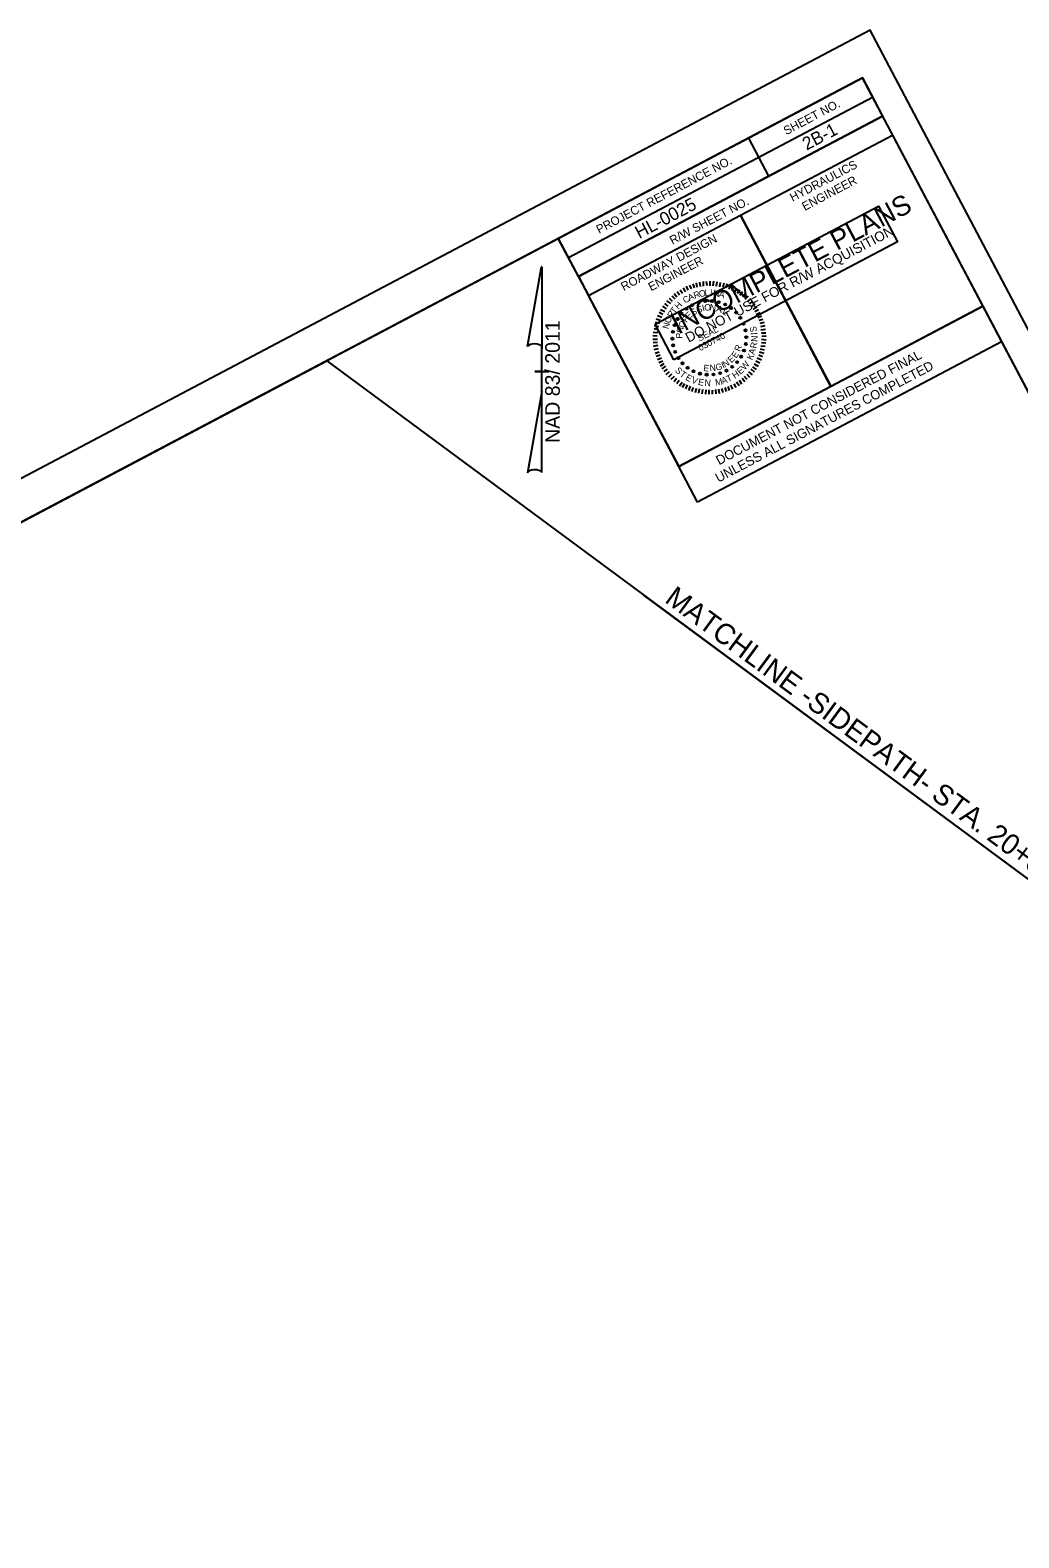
# Model space of a CAD drawing. Extents: x 1487051 to 1489051, y 497582 to 499336.
# Drawn here: x 1488051 to 1488626, y 498459 to 499336 of the extents above; entities that cross this region are included whole.
import ezdxf

# ---------------------------------------------------------------- set-up
doc = ezdxf.new("R2010")
doc.units = 0
for name, color, linetype in [('Matchline', 7, 'Continuous'), ('Matchline Text', 7, 'Continuous'), ('Old_Level_9', 7, 'Continuous'), ('Prop North Arrow NAD83 for Plan Sheets CELL', 7, 'Continuous'), ('Sheet Border Standard 30in CELL', 7, 'Continuous'), ('Sheet Clip Boundary CELL', 7, 'Continuous'), ('Sheet Data Field CELL', 7, 'Continuous'), ('Sheet Plan CELL', 7, 'Continuous'), ('Sheet Plot Border Outside CELL', 7, 'Continuous'), ('Sheet Sticker Exception Certification CELL', 7, 'Continuous'), ('Sheet Sticker Incomplete CELL', 7, 'Continuous')]:
    doc.layers.add(name, color=color, linetype=linetype)

msp = doc.modelspace()

# ---------------------------------------------------------------- linework, layer by layer
at = {"layer": 'Matchline'}
msp.add_line((1488759.65, 498747.81), (1488408.23, 499007.51), dxfattribs=at)
at = {"layer": 'Old_Level_9'}
for p, q in [((1488424.21, 499181.82), (1488425.99, 499179.94)), ((1488425.7, 499183.06), (1488427.26, 499181.18)), ((1488427.42, 499184.31), (1488428.72, 499182.28)), ((1488429.05, 499185.29), (1488430.44, 499183.3)), ((1488430.82, 499186.44), (1488432.03, 499184.14)), ((1488432.67, 499187.42), (1488433.62, 499184.98)), ((1488434.49, 499188.05), (1488435.44, 499185.83)), ((1488436.49, 499188.76), (1488437.17, 499186.41)), ((1488438.36, 499189.29), (1488438.86, 499186.85)), ((1488440.32, 499189.65), (1488440.82, 499187.2)), ((1488442.45, 499190.1), (1488442.51, 499187.42)), ((1488444.33, 499190.19), (1488444.61, 499187.73)), ((1488446.3, 499190.32), (1488446.36, 499187.64)), ((1488448.44, 499190.32), (1488448.14, 499187.68)), ((1488450.47, 499189.92), (1488450.07, 499187.45)), ((1488452.44, 499189.61), (1488451.96, 499187.09)), ((1488454.46, 499189.2), (1488453.89, 499186.87)), ((1488456.31, 499188.71), (1488455.6, 499186.19)), ((1488458.29, 499187.95), (1488457.36, 499185.64)), ((1488460.19, 499187.14), (1488458.99, 499184.92)), ((1488461.91, 499186.24), (1488460.71, 499184.02)), ((1488463.68, 499185.25), (1488462.34, 499183.07)), ((1488465.4, 499184.12), (1488463.79, 499182.03)), ((1488466.9, 499182.99), (1488465.52, 499180.91)), ((1488417.76, 499173.9), (1488420.12, 499172.65)), ((1488418.88, 499175.85), (1488421.07, 499174.28)), ((1488420.1, 499177.39), (1488421.97, 499175.78)), ((1488421.23, 499178.89), (1488423.41, 499177.33)), ((1488422.81, 499180.41), (1488424.55, 499178.61)), ((1488468.59, 499181.51), (1488466.66, 499179.59)), ((1488470.01, 499180.11), (1488468.12, 499178.32)), ((1488471.34, 499178.66), (1488469.36, 499177.05)), ((1488472.49, 499177.12), (1488470.6, 499175.56)), ((1488473.65, 499175.36), (1488471.49, 499173.88)), ((1488474.72, 499173.55), (1488472.51, 499172.38)), ((1488414.08, 499164.6), (1488416.55, 499163.98)), ((1488414.66, 499166.49), (1488417.05, 499165.83)), ((1488415.2, 499168.47), (1488417.5, 499167.54)), ((1488416.01, 499170.37), (1488418.4, 499169.26)), ((1488416.86, 499172.18), (1488419.12, 499171.11)), ((1488475.6, 499171.87), (1488473.39, 499170.7)), ((1488476.5, 499169.97), (1488474.28, 499169.02)), ((1488477.3, 499168.02), (1488474.94, 499167.34)), ((1488477.92, 499166.19), (1488475.38, 499165.65)), ((1488478.37, 499164.28), (1488475.83, 499163.73)), ((1488413.27, 499158.63), (1488415.82, 499158.51)), ((1488413.27, 499156.49), (1488415.96, 499156.55)), ((1488413.5, 499160.56), (1488416.05, 499160.44)), ((1488413.85, 499162.67), (1488416.28, 499162.14)), ((1488478.77, 499162.23), (1488476.05, 499161.81)), ((1488479, 499160.09), (1488476.49, 499160.12)), ((1488479.08, 499156.07), (1488476.49, 499156.28)), ((1488479.08, 499158.21), (1488476.62, 499158.16)), ((1488413.41, 499154.52), (1488416, 499154.76)), ((1488413.59, 499152.47), (1488416.26, 499152.97)), ((1488413.94, 499150.51), (1488416.48, 499151.06)), ((1488414.48, 499148.42), (1488416.93, 499149.14)), ((1488415.1, 499146.6), (1488417.45, 499147.5)), ((1488477.11, 499146.32), (1488474.85, 499147.16)), ((1488477.74, 499148.12), (1488475.26, 499148.96)), ((1488478.23, 499150.19), (1488475.8, 499150.72)), ((1488478.63, 499152.21), (1488476.12, 499152.47)), ((1488479.04, 499154.23), (1488476.35, 499154.4)), ((1488415.91, 499144.65), (1488418.25, 499145.77)), ((1488416.71, 499142.92), (1488419.01, 499143.91)), ((1488417.69, 499141.06), (1488419.8, 499142.41)), ((1488418.71, 499139.34), (1488420.87, 499140.82)), ((1488419.82, 499137.66), (1488421.84, 499139.19)), ((1488472.43, 499137.4), (1488470.34, 499139.01)), ((1488473.51, 499138.99), (1488471.47, 499140.51)), ((1488474.64, 499140.71), (1488472.28, 499141.96)), ((1488475.45, 499142.61), (1488473.19, 499143.68)), ((1488476.44, 499144.38), (1488473.95, 499145.44)), ((1488421.02, 499136.04), (1488422.95, 499137.73)), ((1488422.44, 499134.64), (1488424.28, 499136.29)), ((1488423.94, 499133.28), (1488425.74, 499135.02)), ((1488425.58, 499131.89), (1488427.06, 499133.8)), ((1488427.09, 499130.76), (1488428.52, 499132.76)), ((1488428.77, 499129.5), (1488430.24, 499131.63)), ((1488430.4, 499128.55), (1488431.74, 499130.73)), ((1488432.39, 499127.57), (1488433.41, 499129.91)), ((1488434.2, 499126.71), (1488435.04, 499129.19)), ((1488459.81, 499127.46), (1488458.69, 499129.8)), ((1488461.72, 499128.35), (1488460.55, 499130.56)), ((1488463.35, 499129.33), (1488461.96, 499131.53)), ((1488465.03, 499130.44), (1488463.64, 499132.42)), ((1488466.74, 499131.68), (1488465.13, 499133.66)), ((1488468.19, 499133.01), (1488466.54, 499134.85)), ((1488469.68, 499134.25), (1488468.03, 499136.09)), ((1488471.12, 499135.81), (1488469.07, 499137.55)), ((1488436, 499126.08), (1488436.89, 499128.47)), ((1488438.07, 499125.59), (1488438.6, 499128.02)), ((1488439.91, 499125.09), (1488440.35, 499127.7)), ((1488441.94, 499124.69), (1488442.28, 499127.25)), ((1488444.04, 499124.56), (1488444.16, 499127.11)), ((1488446.01, 499124.47), (1488446, 499127.06)), ((1488448.02, 499124.51), (1488447.97, 499126.97)), ((1488450.08, 499124.69), (1488449.84, 499127.28)), ((1488452.08, 499124.96), (1488451.67, 499127.46)), ((1488454.13, 499125.59), (1488453.45, 499127.94)), ((1488456.04, 499126.03), (1488455.32, 499128.48)), ((1488457.86, 499126.65), (1488457.01, 499128.92))]:
    msp.add_line(p, q, dxfattribs=at)
for centre in [(1488432.81, 499174.19), (1488436.14, 499176.35), (1488439.81, 499177.86), (1488443.69, 499178.66), (1488447.66, 499178.74), (1488451.57, 499178.09), (1488455.29, 499176.73), (1488458.71, 499174.71), (1488425.91, 499164.67), (1488427.61, 499168.25), (1488429.93, 499171.47), (1488461.69, 499172.1), (1488464.14, 499168.98), (1488465.98, 499165.47), (1488424.62, 499156.88), (1488424.9, 499160.83), (1488467.14, 499161.68), (1488467.58, 499157.74), (1488425.06, 499152.94), (1488426.22, 499149.15), (1488464.59, 499146.36), (1488466.29, 499149.95), (1488467.3, 499153.78), (1488428.06, 499145.63), (1488430.51, 499142.52), (1488433.5, 499139.91), (1488436.91, 499137.89), (1488456.06, 499138.27), (1488459.39, 499140.42), (1488462.27, 499143.15), (1488440.63, 499136.53), (1488444.54, 499135.88), (1488448.51, 499135.96), (1488452.39, 499136.76)]:
    msp.add_circle(centre, 0.63, dxfattribs=at)
at = {"layer": 'Prop North Arrow NAD83 for Plan Sheets CELL'}
for p, q in [((1488340.33, 499152.33), (1488348.53, 499198.68)), ((1488348.58, 499198.68), (1488348.53, 499198.68)), ((1488348.58, 499198.68), (1488348.53, 499198.68)), ((1488348.58, 499198.68), (1488348.58, 499150.88)), ((1488348.58, 499126.08), (1488348.58, 499152.28)), ((1488348.58, 499150.88), (1488348.58, 499152.23)), ((1488344.58, 499137.68), (1488344.53, 499137.68)), ((1488348.13, 499137.68), (1488344.58, 499137.68)), ((1488344.63, 499137.68), (1488352.63, 499137.68)), ((1488348.58, 499126.08), (1488340.23, 499078.83)), ((1488348.63, 499079.03), (1488348.58, 499126.08))]:
    msp.add_line(p, q, dxfattribs=at)
for centre, start_param, end_param in [((1488344.46, 499151.83), 0.216388, 2.908219), ((1488344.46, 499078.66), 0.201328, 3.141593)]:
    msp.add_ellipse(centre, major_axis=(4.23, -0.03), ratio=0.461098, start_param=start_param, end_param=end_param, dxfattribs=at)
at = {"layer": 'Sheet Border Standard 30in CELL'}
msp.add_line((1488369.9, 499192.95), (1488375.74, 499181.9), dxfattribs=at)
at = {"layer": 'Sheet Clip Boundary CELL'}
msp.add_lwpolyline([(1487208.66, 498608.09), (1488223.53, 499144), (1488876.96, 498661.12), (1489025.39, 498380), (1487698.94, 497679.61)], close=True, dxfattribs=at)
at = {"layer": 'Sheet Plan CELL'}
for p, q in [((1488364.06, 499204.02), (1488540.97, 499297.41)), ((1488369.93, 499192.94), (1488546.81, 499286.36)), ((1488369.93, 499192.94), (1488546.81, 499286.36)), ((1488468.8, 499273.43), (1488480.51, 499251.34)), ((1488464.23, 499228.61), (1488516.75, 499129.17)), ((1488369.93, 499192.94), (1488375.76, 499181.89))]:
    msp.add_line(p, q, dxfattribs=at)
for points in [[(1488535.14, 499308.53), (1487208.67, 498608.12), (1487698.94, 497679.61), (1489025.4, 498380.01)], [(1488358.21, 499215.12), (1488535.14, 499308.53), (1488546.81, 499286.36), (1488369.93, 499192.94)], [(1488464.23, 499228.61), (1488552.64, 499275.31), (1488605.19, 499175.82), (1488516.77, 499129.11)], [(1488375.76, 499181.89), (1488464.23, 499228.61), (1488516.77, 499129.11), (1488428.29, 499082.43)], [(1487698.94, 497679.61), (1487208.66, 498608.09), (1488358.21, 499215.12), (1488428.29, 499082.43), (1488605.19, 499175.82), (1489025.4, 498380.01)]]:
    msp.add_lwpolyline(points, close=True, dxfattribs=at)
at = {"layer": 'Sheet Plot Border Outside CELL'}
msp.add_lwpolyline([(1487562.23, 497581.96), (1489050.94, 498368.04), (1488539.66, 499336.34), (1487050.94, 498550.27)], close=True, dxfattribs=at)
at = {"layer": 'Sheet Sticker Exception Certification CELL'}
for p, q in [((1488428.29, 499082.43), (1488605.18, 499175.83)), ((1488428.29, 499082.43), (1488605.18, 499175.83)), ((1488605.19, 499175.82), (1488616.16, 499155.04)), ((1488605.19, 499175.82), (1488616.16, 499155.04)), ((1488616.16, 499155.05), (1488439.27, 499061.65)), ((1488616.16, 499155.05), (1488439.27, 499061.65)), ((1488439.27, 499061.65), (1488428.29, 499082.43)), ((1488439.27, 499061.65), (1488428.29, 499082.43))]:
    msp.add_line(p, q, dxfattribs=at)
at = {"layer": 'Sheet Sticker Incomplete CELL'}
msp.add_lwpolyline([(1488425.5, 499144.55), (1488414.53, 499165.33), (1488544.52, 499233.97), (1488555.49, 499213.19)], close=True, dxfattribs=at)

# ---------------------------------------------------------------- texts
at = {"layer": 'Matchline Text'}
msp.add_text('MATCHLINE -SIDEPATH- STA. 20+00 SEE SHEET 2B-2', height=12, rotation=323.61305, dxfattribs=at).set_placement((1488419.52, 499003.95))
at = {"layer": 'Old_Level_9'}
for s, height, rotation, p in [('C', 3.78, 32.77501, (1488432.1, 499177.17)), ('A', 3.78, 25.80995, (1488434.57, 499178.7)), ('R', 3.78, 17.85665, (1488437.58, 499180.06)), ('O', 3.78, 10.92189, (1488440.38, 499180.97)), ('L', 3.78, 3.581, (1488443.45, 499181.58)), ('I', 3.78, 358.64105, (1488446.67, 499181.7)), ('N', 3.78, 352.73893, (1488448.14, 499181.68)), ('A', 3.78, 344.84016, (1488451.24, 499181.17)), ('R', 3.78, 60.01054, (1488424.55, 499168.55)), ('T', 3.78, 53.27087, (1488426.02, 499170.9)), ('H', 3.78, 45.57844, (1488428.1, 499173.59)), ('S', 3.76, 32.30312, (1488436.55, 499170.02)), ('S', 3.76, 20.87655, (1488439.33, 499171.6)), ('I', 3.76, 13.31716, (1488442.35, 499172.74)), ('O', 3.76, 5.70998, (1488443.33, 499173.03)), ('N', 3.76, 355.22811, (1488446.23, 499173.32)), ('A', 3.76, 341.77886, (1488449.86, 499172.86)), ('L', 3.76, 329.3674, (1488453.24, 499171.6)), ('N', 3.78, 75.90175, (1488422.36, 499162.19)), ('O', 3.78, 67.77931, (1488423.14, 499165.43)), ('O', 3.76, 66.08691, (1488431.25, 499162.7)), ('F', 3.76, 54.23505, (1488432.84, 499165.91)), ('E', 3.76, 44.42402, (1488434.27, 499167.91)), ('P', 3.76, 87.95873, (1488430.4, 499156.82)), ('R', 3.76, 77.58289, (1488430.6, 499159.87)), ('SEAL', 3.759, 27.83509, (1488440.4, 499155.13)), ('030740', 3.759, 27.83509, (1488440.87, 499149.54)), ('S', 3.78, 100.09298, (1488473.85, 499161.01)), ('I', 3.78, 93.88149, (1488474.02, 499159.18)), ('N', 3.78, 87.20766, (1488474.09, 499154.92)), ('E', 3.76, 43.64078, (1488458.9, 499142.47)), ('E', 3.76, 54.9919, (1488461.66, 499145.17)), ('R', 3.76, 68.18435, (1488463.9, 499149.06)), ('K', 3.78, 63.9761, (1488470.97, 499144.02)), ('A', 3.78, 71.35678, (1488472.23, 499147.26)), ('R', 3.78, 78.98541, (1488473.43, 499150.91)), ('S', 3.78, 316.0471, (1488425.8, 499138.02)), ('T', 3.78, 323.45948, (1488428.49, 499135.46)), ('E', 3.76, 352.70428, (1488442.45, 499138.08)), ('N', 3.76, 3.89345, (1488446.39, 499137.9)), ('G', 3.76, 15.31634, (1488450.23, 499138.12)), ('I', 3.76, 23.45968, (1488454.09, 499139.36)), ('N', 3.76, 30.96288, (1488455.15, 499139.92)), ('H', 3.78, 33.84631, (1488460.92, 499133.4)), ('E', 3.78, 41.99985, (1488464.13, 499135.75)), ('W', 3.78, 49.84085, (1488466.74, 499138.22)), ('E', 3.78, 331.65758, (1488431.86, 499133.08)), ('V', 3.78, 339.76489, (1488435.35, 499131.32)), ('E', 3.78, 348.06633, (1488439.29, 499130.04)), ('N', 3.78, 356.16408, (1488443.19, 499129.36)), ('M', 3.78, 10.17213, (1488449.82, 499129.46)), ('A', 3.78, 18.01726, (1488453.74, 499130.37)), ('T', 3.78, 25.22168, (1488457.02, 499131.47))]:
    msp.add_text(s, height=height, rotation=rotation, dxfattribs=at).set_placement(p)
at = {"layer": 'Prop North Arrow NAD83 for Plan Sheets CELL'}
msp.add_text('NAD 83/ 2011', height=8.5, rotation=90, dxfattribs=at).set_placement((1488359.1, 499096.16))
at = {"layer": 'Sheet Data Field CELL'}
for s, p in [('2B-1', (1488502.69, 499266.23)), ('HL-0025', (1488405.34, 499214.76))]:
    msp.add_text(s, height=7.5, rotation=27.8351, dxfattribs=at).set_placement(p)
at = {"layer": 'Sheet Plan CELL'}
for s, height, p in [('SHEET NO.', 5, (1488490.88, 499275.18)), ('PROJECT REFERENCE NO.', 5.0001, (1488381.92, 499217.77)), ('HYDRAULICS', 5, (1488494.57, 499236.4)), ('ENGINEER', 5, (1488501.61, 499231.12)), ('R/W SHEET NO.', 5.0001, (1488424.62, 499211.43)), ('ROADWAY DESIGN', 5.0001, (1488396.3, 499184.48)), ('ENGINEER', 5, (1488412.19, 499184.35))]:
    msp.add_text(s, height=height, rotation=27.8351, dxfattribs=at).set_placement(p)
at = {"layer": 'Sheet Sticker Exception Certification CELL'}
for s, p in [('DOCUMENT NOT CONSIDERED FINAL', (1488451.76, 499083.12)), ('DOCUMENT NOT CONSIDERED FINAL', (1488451.76, 499083.12)), ('UNLESS ALL SIGNATURES COMPLETED', (1488451.38, 499072.97)), ('UNLESS ALL SIGNATURES COMPLETED', (1488451.38, 499072.97))]:
    msp.add_text(s, height=5.5, rotation=27.83509, dxfattribs=at).set_placement(p)
at = {"layer": 'Sheet Sticker Incomplete CELL'}
for s, height, p in [('INCOMPLETE PLANS', 11.52, (1488427.95, 499159.07)), ('DO NOT USE FOR R/W ACQUISITION', 5.76, (1488434.07, 499154.45))]:
    msp.add_text(s, height=height, rotation=27.83509, dxfattribs=at).set_placement(p)

doc.saveas('drawing.dxf')
